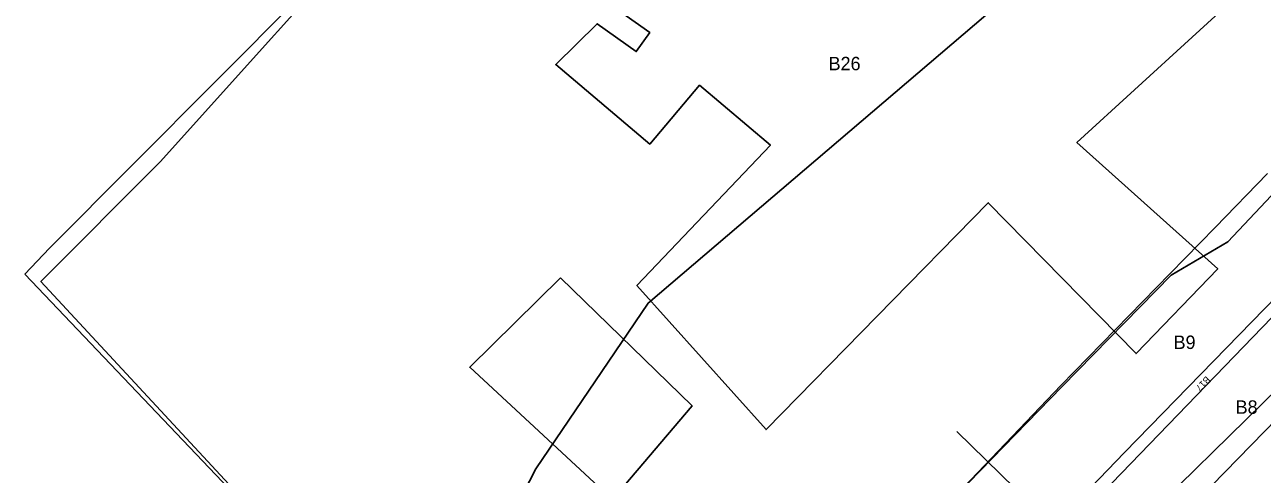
# Model space of a CAD drawing. Extents: x 2253035 to 2279930, y 13774972 to 13793443.
# Drawn here: x 2255334 to 2256071, y 13791870 to 13792138 of the extents above; entities that cross this region are included whole.
import ezdxf

# ---------------------------------------------------------------- set-up
doc = ezdxf.new("R2010")
doc.units = 0
for name, color, linetype in [('E_Utility_ATT_Fiber', 7, 'Continuous'), ('E_Utility_Electric_Power Pole_PP_Description', 7, 'Continuous'), ('E_Utility_Gas_Gas Line_GL_Description', 7, 'Continuous'), ('E_Utility_Gas_Gas Line_GL_Elevation', 7, 'Continuous'), ('E_Utility_Water_Valve Cover Water_VCW_point', 7, 'Continuous'), ('E_Utility_Water_Water Line_WL_Description', 7, 'Continuous'), ('E_Utility_Water_Water Line_WL_Elevation', 7, 'Continuous'), ('E_Utility_Water_Water Valve_WV_Elevation', 7, 'Continuous')]:
    doc.layers.add(name, color=color, linetype=linetype)

msp = doc.modelspace()

# ---------------------------------------------------------------- linework, layer by layer
at = {"layer": 'E_Utility_ATT_Fiber'}
for p, q in [((2255552.69, 13792209.6), (2255348.72, 13792004.63)), ((2256043.35, 13792017.03), (2256074.64, 13792049.12)), ((2256074.64, 13792049.12), (2256043.35, 13792017.03)), ((2256016.63, 13791989.63), (2256043.35, 13792017.03)), ((2256043.35, 13792017.03), (2256016.63, 13791989.63)), ((2255348.72, 13792004.63), (2255334.02, 13791989.22)), ((2255334.02, 13791989.22), (2255605.72, 13791703.85)), ((2255951.39, 13791922.73), (2256016.63, 13791989.63)), ((2256016.63, 13791989.63), (2255951.39, 13791922.73)), ((2255889.49, 13791857.83), (2255951.39, 13791922.73)), ((2255951.39, 13791922.73), (2255889.49, 13791857.83))]:
    msp.add_line(p, q, dxfattribs=at)
msp.add_lwpolyline([(2256171.13, 13792017.36), (2256192.1, 13792017.74), (2256119.93, 13791943.73), (2256025.48, 13791846.89), (2255967.21, 13791785.59), (2255941.93, 13791781.43), (2255934.04, 13791825.57), (2255989.41, 13791882.95), (2256156.41, 13792054.2)], close=True, dxfattribs=at)
msp.add_lwpolyline([(2255934.04, 13791825.57), (2255989.41, 13791882.95), (2256156.41, 13792054.2)], dxfattribs=at)
at = {"layer": 'E_Utility_Electric_Power Pole_PP_Description'}
msp.add_line((2255889.33, 13791895.46), (2256027.49, 13791760.72), dxfattribs=at)
at = {"layer": 'E_Utility_Gas_Gas Line_GL_Description'}
msp.add_line((2256154.01, 13792043.13), (2255927.7, 13791808.58), dxfattribs=at)
at = {"layer": 'E_Utility_Water_Valve Cover Water_VCW_point'}
msp.add_lwpolyline([(2256182.36, 13792333.03), (2256020.17, 13792240.46), (2255705.5, 13791971.89), (2255638.6, 13791873.25), (2255619.92, 13791836.72), (2255688.63, 13791652.45)], dxfattribs=at)
at = {"layer": 'E_Utility_Water_Water Line_WL_Description'}
msp.add_lwpolyline([(2255674.85, 13792155.59), (2255706.41, 13792133.11), (2255698.35, 13792121.79), (2255675.07, 13792138.37), (2255650.47, 13792113.98), (2255706.41, 13792066.63), (2255736.11, 13792101.71), (2255778.38, 13792065.93), (2255698.76, 13791982.45), (2255775.73, 13791896.53), (2255908.16, 13792031.71), (2255996.22, 13791941.84), (2256044.94, 13791992.32), (2255960.96, 13792067.58), (2256063.98, 13792161.92)], dxfattribs=at)
msp.add_lwpolyline([(2255653.29, 13791986.95), (2255731.7, 13791910.7), (2255684.16, 13791854.94), (2255599.2, 13791933.65)], close=True, dxfattribs=at)
at = {"layer": 'E_Utility_Water_Water Line_WL_Elevation'}
msp.add_lwpolyline([(2255552.69, 13792209.6), (2255414.64, 13792056.03), (2255343.69, 13791984.84), (2255605.99, 13791701.86), (2255609.85, 13791705.81), (2255620.44, 13791716), (2255687.16, 13791650.79), (2255732.69, 13791697.37), (2255738.56, 13791691.61), (2255743.07, 13791696.22), (2255737.22, 13791701.96), (2255882.44, 13791850.6), (2255952.2, 13791922.14), (2256017.05, 13791988.64), (2256050.99, 13792008.43), (2256083.27, 13792042.75), (2256102.42, 13792056.55), (2256121.52, 13792085.4), (2256170.83, 13792144.18)], dxfattribs=at)
at = {"layer": 'E_Utility_Water_Water Valve_WV_Elevation'}
msp.add_lwpolyline([(2255390.98, 13791330.06), (2255459.85, 13791397.22), (2255383.32, 13791459.9), (2255493.57, 13791567.11), (2255547.29, 13791645.62), (2255605.99, 13791701.86), (2255343.69, 13791984.84), (2255414.64, 13792056.03), (2255552.69, 13792209.6), (2256003.03, 13792697.26), (2256274.85, 13792371.04), (2256429.6, 13792200.7), (2256502.73, 13792117.35), (2256310.07, 13791948.12), (2256237.1, 13792031.76), (2256159.74, 13792001.95), (2256121.45, 13791961.04), (2255952.32, 13791795.31), (2255623, 13791457.45), (2255517, 13791344.43)], dxfattribs=at)

# ---------------------------------------------------------------- texts
at = {"layer": 'E_Utility_Gas_Gas Line_GL_Elevation'}
for s, p in [('B26', (2255813.02, 13792110.63)), ('B9', (2256018.59, 13791944.56)), ('B8', (2256055.57, 13791905.96))]:
    msp.add_text(s, height=8, dxfattribs=at).set_placement(p)
msp.add_text('B17', height=4, rotation=226.02445, dxfattribs=at).set_placement((2256037.97, 13791928.63))

doc.saveas('drawing.dxf')
